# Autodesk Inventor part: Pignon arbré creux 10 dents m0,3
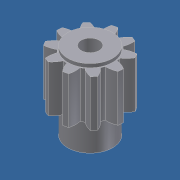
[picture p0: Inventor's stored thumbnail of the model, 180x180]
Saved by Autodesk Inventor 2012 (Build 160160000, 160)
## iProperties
Created: 2011-10
Part Number: Pignon arbré creux 10 dents m0,3
Document SubType Name: Modeling
Designer: Laur
Density: 1 g/cm^3
Material: Par défaut
Author: Laur
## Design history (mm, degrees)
derived "Pignon arbré creux 10 dents m0,3.iam"
node "Solide1"
node "Corps solides"
node "Corps surfaciques"
node "arbre creux inter.ipt:1"
sketch "Engrenages cylindriques:1::Engrenage cylindrique1:1"
